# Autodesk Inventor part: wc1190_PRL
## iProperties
Shininess: 64.0
Length Units: 11272
Angle Units: 11279
Time Units: 11290
Mass Units: 11286
Length Display Precision: 3
Angle Display Precision: 2
Compacted: True
Part Number: wc1190_PRL
Document SubType Name: Modeling
Created: 2004-08
Designer: John Blackburn
Manufacturer: Standard
Standards Organization: Custom
Material: Phenolic
Density: 0.0
Volumn: 0.0
Area: 0.0
PropertySet Name: Model Information
Control State: 0
Master: False
Checked Out: False
Author: John Blackburn
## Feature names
1. Revolution1
